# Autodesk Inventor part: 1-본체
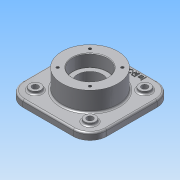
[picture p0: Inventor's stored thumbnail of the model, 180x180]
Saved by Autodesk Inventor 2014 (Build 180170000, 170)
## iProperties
Created: 2015-09
Part Number: 1-본체
Material: 알루미늄 6061
Document SubType Name: Modeling
Designer: study
Density: 2.71 g/cm^3
Appearance: 알루미늄 - 평지
Author: study
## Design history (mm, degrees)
sketch "스케치1"
  geometry: L1 (75, -75)-(-75, -75); L2 (-75, -75)-(-75, 75); L3 (-75, 75)-(75, 75); L4 (75, 75)-(75, -75); 2 further points
  constraints: 8 end point, 1 coincident, 1 vertical, 9 other
  dimensions: "d0" = 150 distance of L2.end L3.end
extrude "돌출1" new body sketch "스케치1" distance "d1" = 12; taper "d2" = 0 deg
node "작업 평면1"
sketch "스케치2"
  geometry: C1 r 50 at (0, 0); 1 further point
  constraints: 1 centre point, 1 coincident
  dimensions: "d4" = 100 diameter of C1
extrude "돌출2" join sketch "스케치2" distance "d5" = 70; taper "d6" = 0 deg
sketch "스케치3"
  geometry: L1 (-49, 49)-(49, 49); L2 (49, 49)-(49, -49); L3 (49, -49)-(-49, -49); L4 (-49, -49)-(-49, 49); L5 (-49, 49)-(49, -49); L6 (49, 49)-(-49, -49); C1 r 50 at (0, 0) reference; C2 r 10 at (-49, 49); C3 r 10 at (49, 49); C4 r 10 at (49, -49); C5 r 10 at (-49, -49)
  constraints: 12 end point, 4 centre point, 4 coincident, 3 equal radius, 2 midpoint, 2 parallel, 1 horizontal, 1 perpendicular
  dimensions: "d7" = 98 distance of L1.start L1.end; "d8" = 98 distance of L3.end L1.start; "d9" = 20 diameter of C2
extrude "돌출3" join sketch "스케치3" distance "d10" = 5; taper "d11" = 0 deg
hole "구멍1" diameter "d14" = 45; stored, may be unused: countersink angle "d18" = 90 deg, drill point angle "d20" = 0 deg; dims "d12" = 10, "d13" = 10, "d15" = 6, "d16" = 62, "d17" = 22, "d19" = 8
hole "구멍2" diameter "d23" = 45; stored, may be unused: countersink angle "d27" = 90 deg, drill point angle "d29" = 0 deg; dims "d21" = 10, "d22" = 10, "d24" = 6, "d25" = 62, "d26" = 22, "d28" = 8
sketch "스케치4"
  geometry: L1 (0, 0)-(-41, 0); L2 (0, 0)-(-28.991, 28.991); C1 r 50 at (0, 0) reference; A1 r 41 centre (0, 0) between (-41, 0) and (-28.991, 28.991); 1 further point
  constraints: 4 end point, 2 coincident, 2 point on circle, 1 centre point, 1 horizontal
  dimensions: "d30" = 82 diameter of A1; "d32" = 45 deg angle of L1 L2
hole "구멍3" sketch "스케치4" at (-28.991, 28.991) diameter "d33" = 4.917; stored, may be unused: countersink angle "d37" = 90 deg, drill point angle "d39" = 118 deg; dims "d34" = 10, "d35" = 62, "d36" = 22, "d38" = 13
node "작업 평면2"
hole "구멍4" diameter "d45" = 11; stored, may be unused: countersink angle "d49" = 90 deg, drill point angle "d51" = 118 deg; dims "d43" = 10, "d44" = 10, "d46" = 10, "d47" = 62, "d48" = 22, "d50" = 13
hole "구멍5" diameter "d54" = 11; stored, may be unused: countersink angle "d58" = 90 deg, drill point angle "d60" = 118 deg; dims "d52" = 10, "d53" = 10, "d55" = 10, "d56" = 62, "d57" = 22, "d59" = 13
hole "구멍6" diameter "d63" = 11; stored, may be unused: countersink angle "d67" = 90 deg, drill point angle "d69" = 118 deg; dims "d61" = 10, "d62" = 10, "d64" = 10, "d65" = 62, "d66" = 22, "d68" = 13
hole "구멍7" diameter "d72" = 11; stored, may be unused: countersink angle "d76" = 90 deg, drill point angle "d78" = 118 deg; dims "d70" = 10, "d71" = 10, "d73" = 10, "d74" = 62, "d75" = 22, "d77" = 13
sketch "스케치5"
  geometry: C1 r 50 at (0, 0) reference; 1 further point
  constraints: 1 vertical alignment, 1 other
  dimensions: "d79" = 65 distance of point (0, 65) C1.centre
feature "엠보싱1" sketch "스케치5" dims "d0" = 150, "d9" = 20, "d80" = 1, "d81" = 0
chamfer "모따기1" distance "d82" = 1; stored, may be unused: second distance "d83" = 2, angle "d84" = 45 deg
fillet "모깎기1" dims "d85" = 0.3, "d86" = 30
fillet "모깎기2" dims "d87" = 3
node "솔리드1"
pattern_circular "원형 패턴1" dims angle "d41" = 360 deg
mirror "대칭1"
other parameters: "d3" = 23
